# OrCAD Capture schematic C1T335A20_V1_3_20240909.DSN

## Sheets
1 005_SDM: size A4; title: TELINK; rev: V1.3; note: C1T335A20
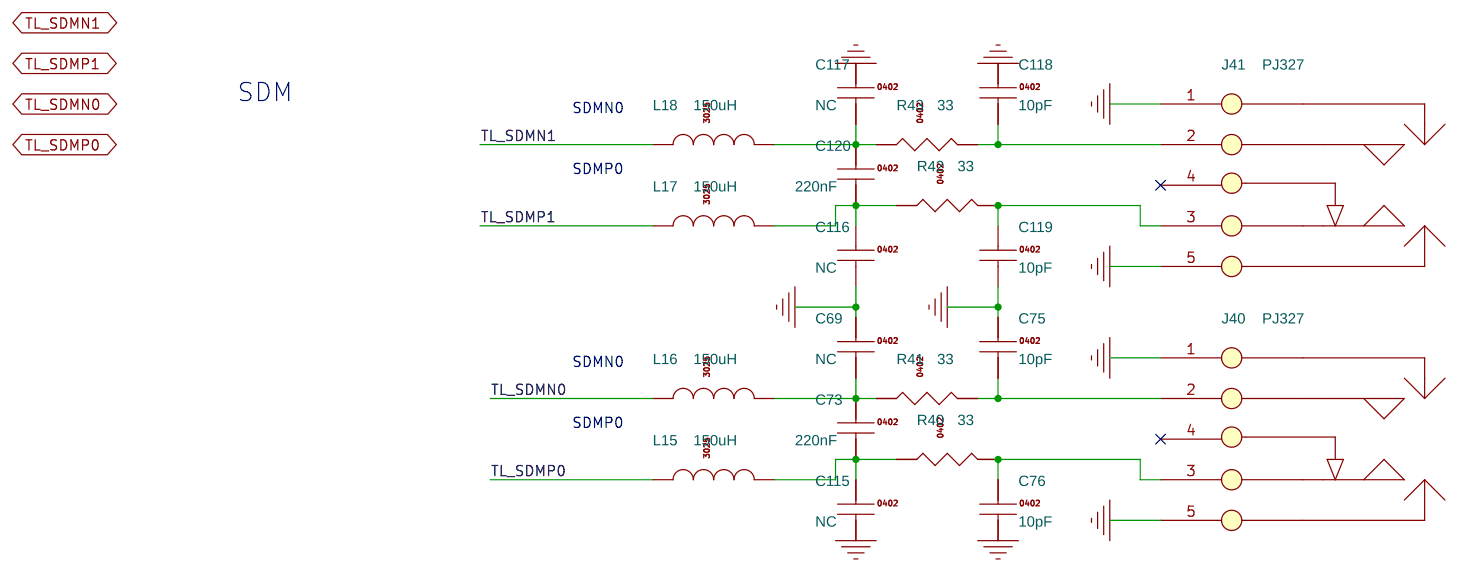
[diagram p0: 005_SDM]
2 000_LOG
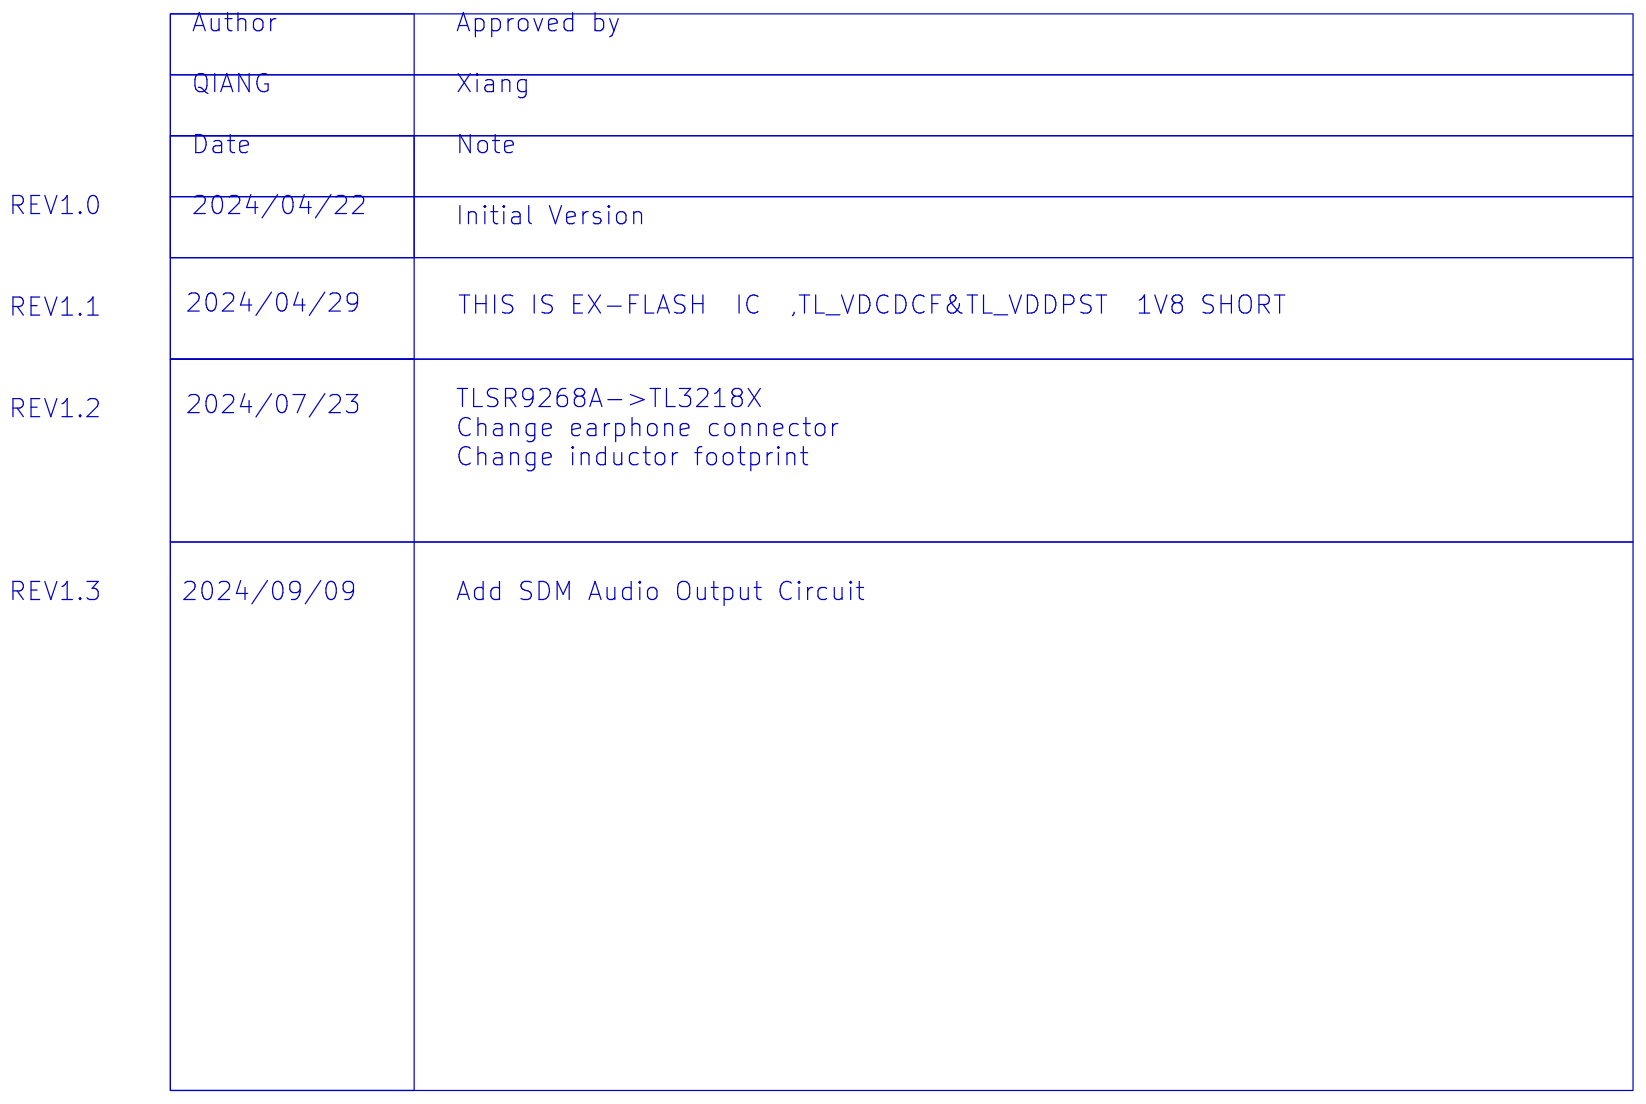
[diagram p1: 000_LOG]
3 001_STR
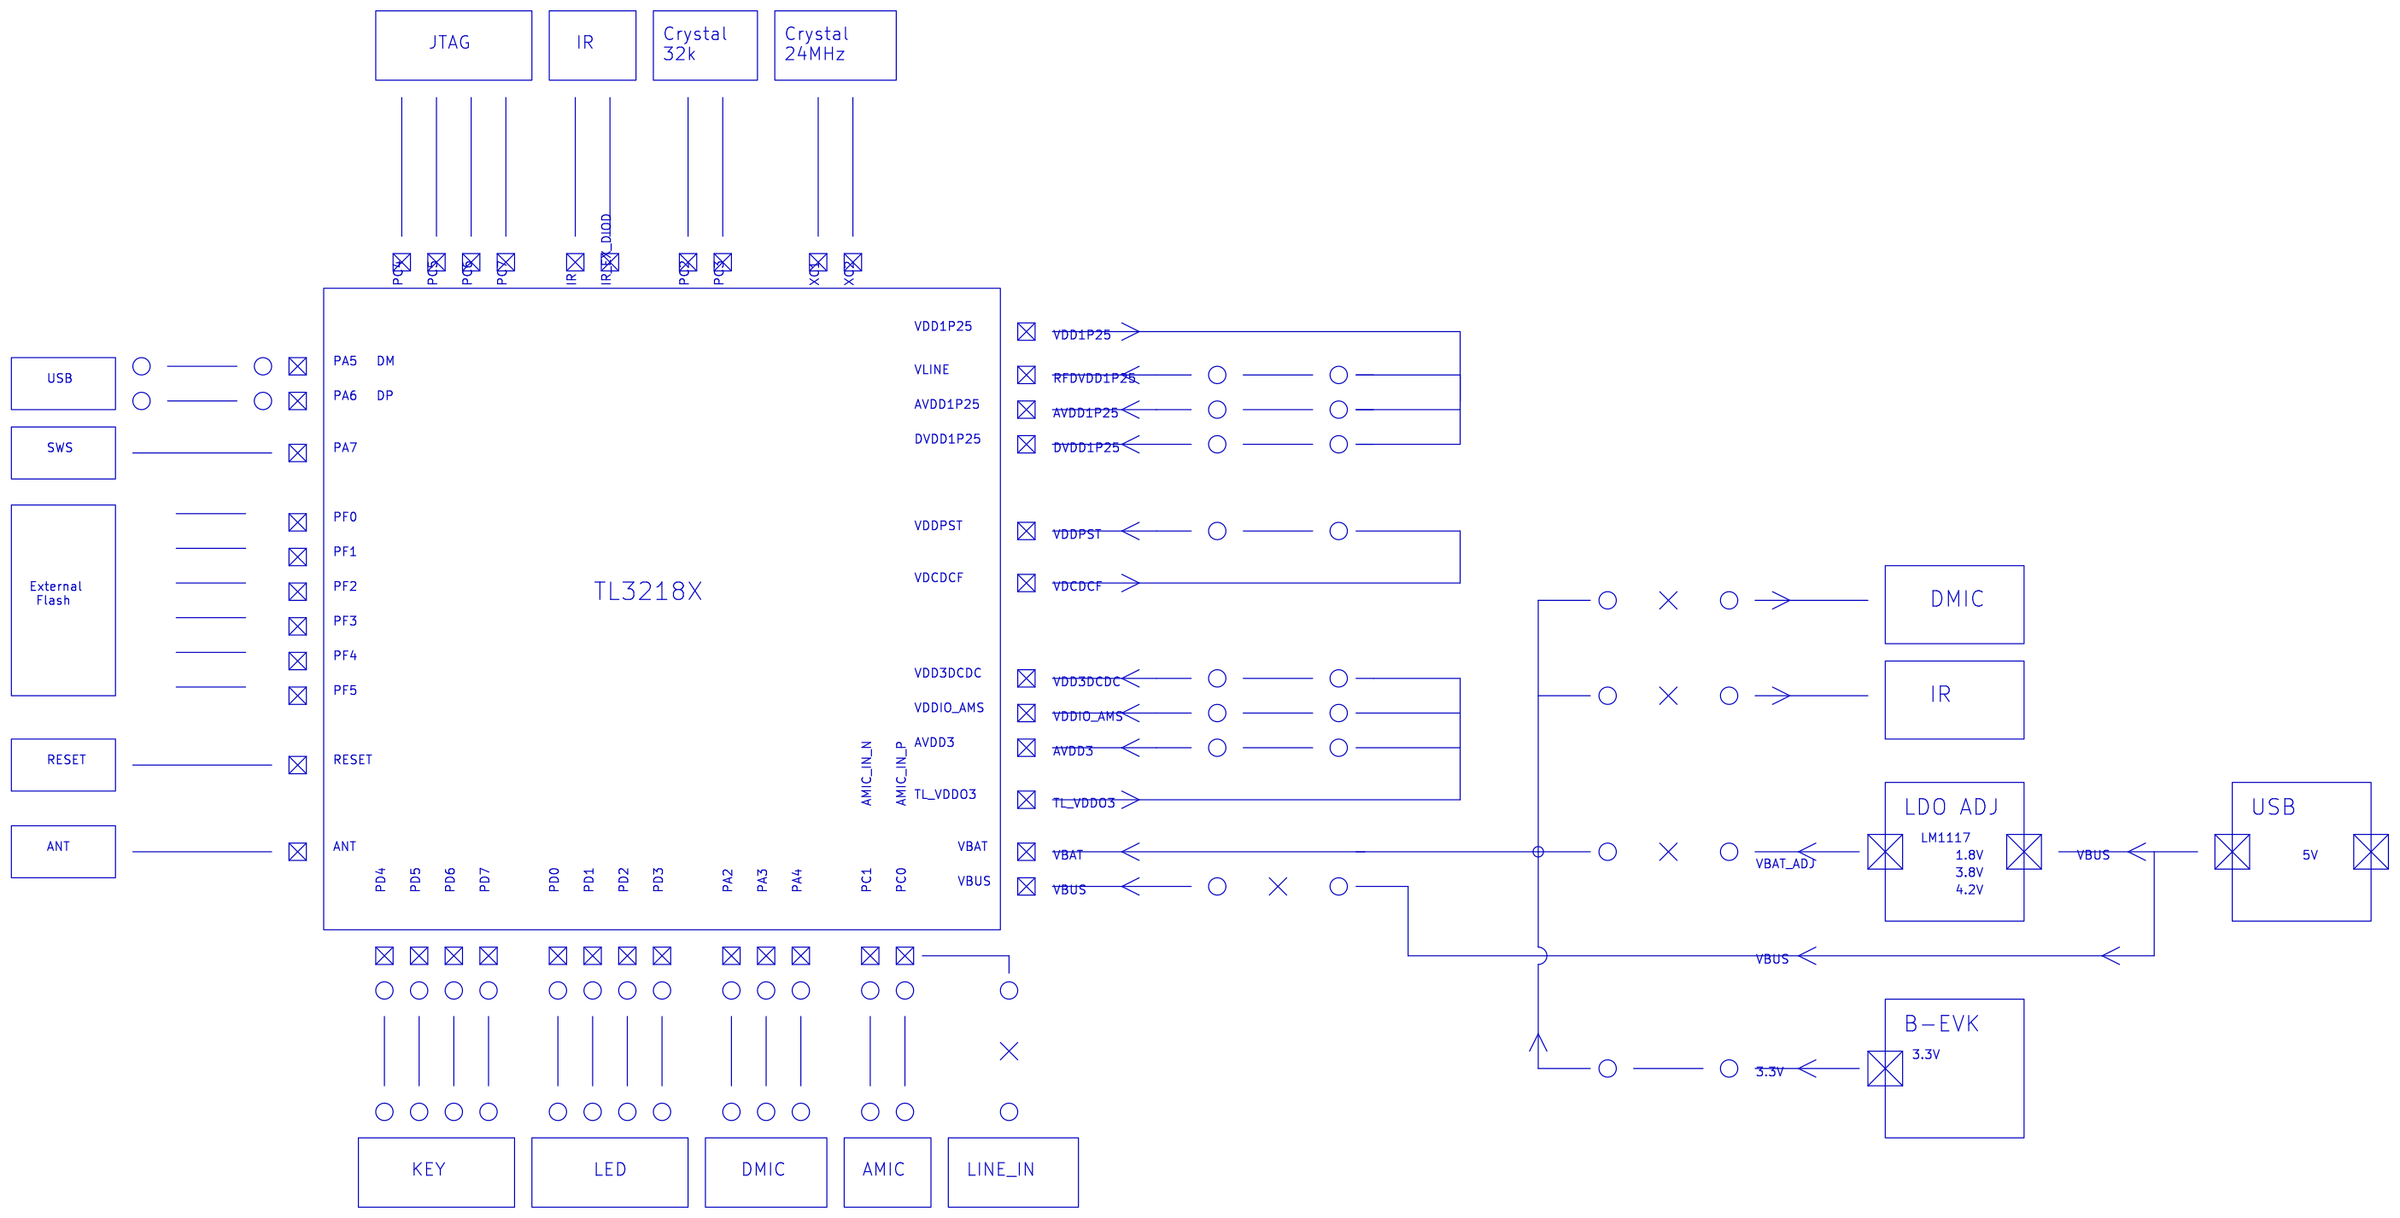
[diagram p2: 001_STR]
4 002_MAIN: size A3
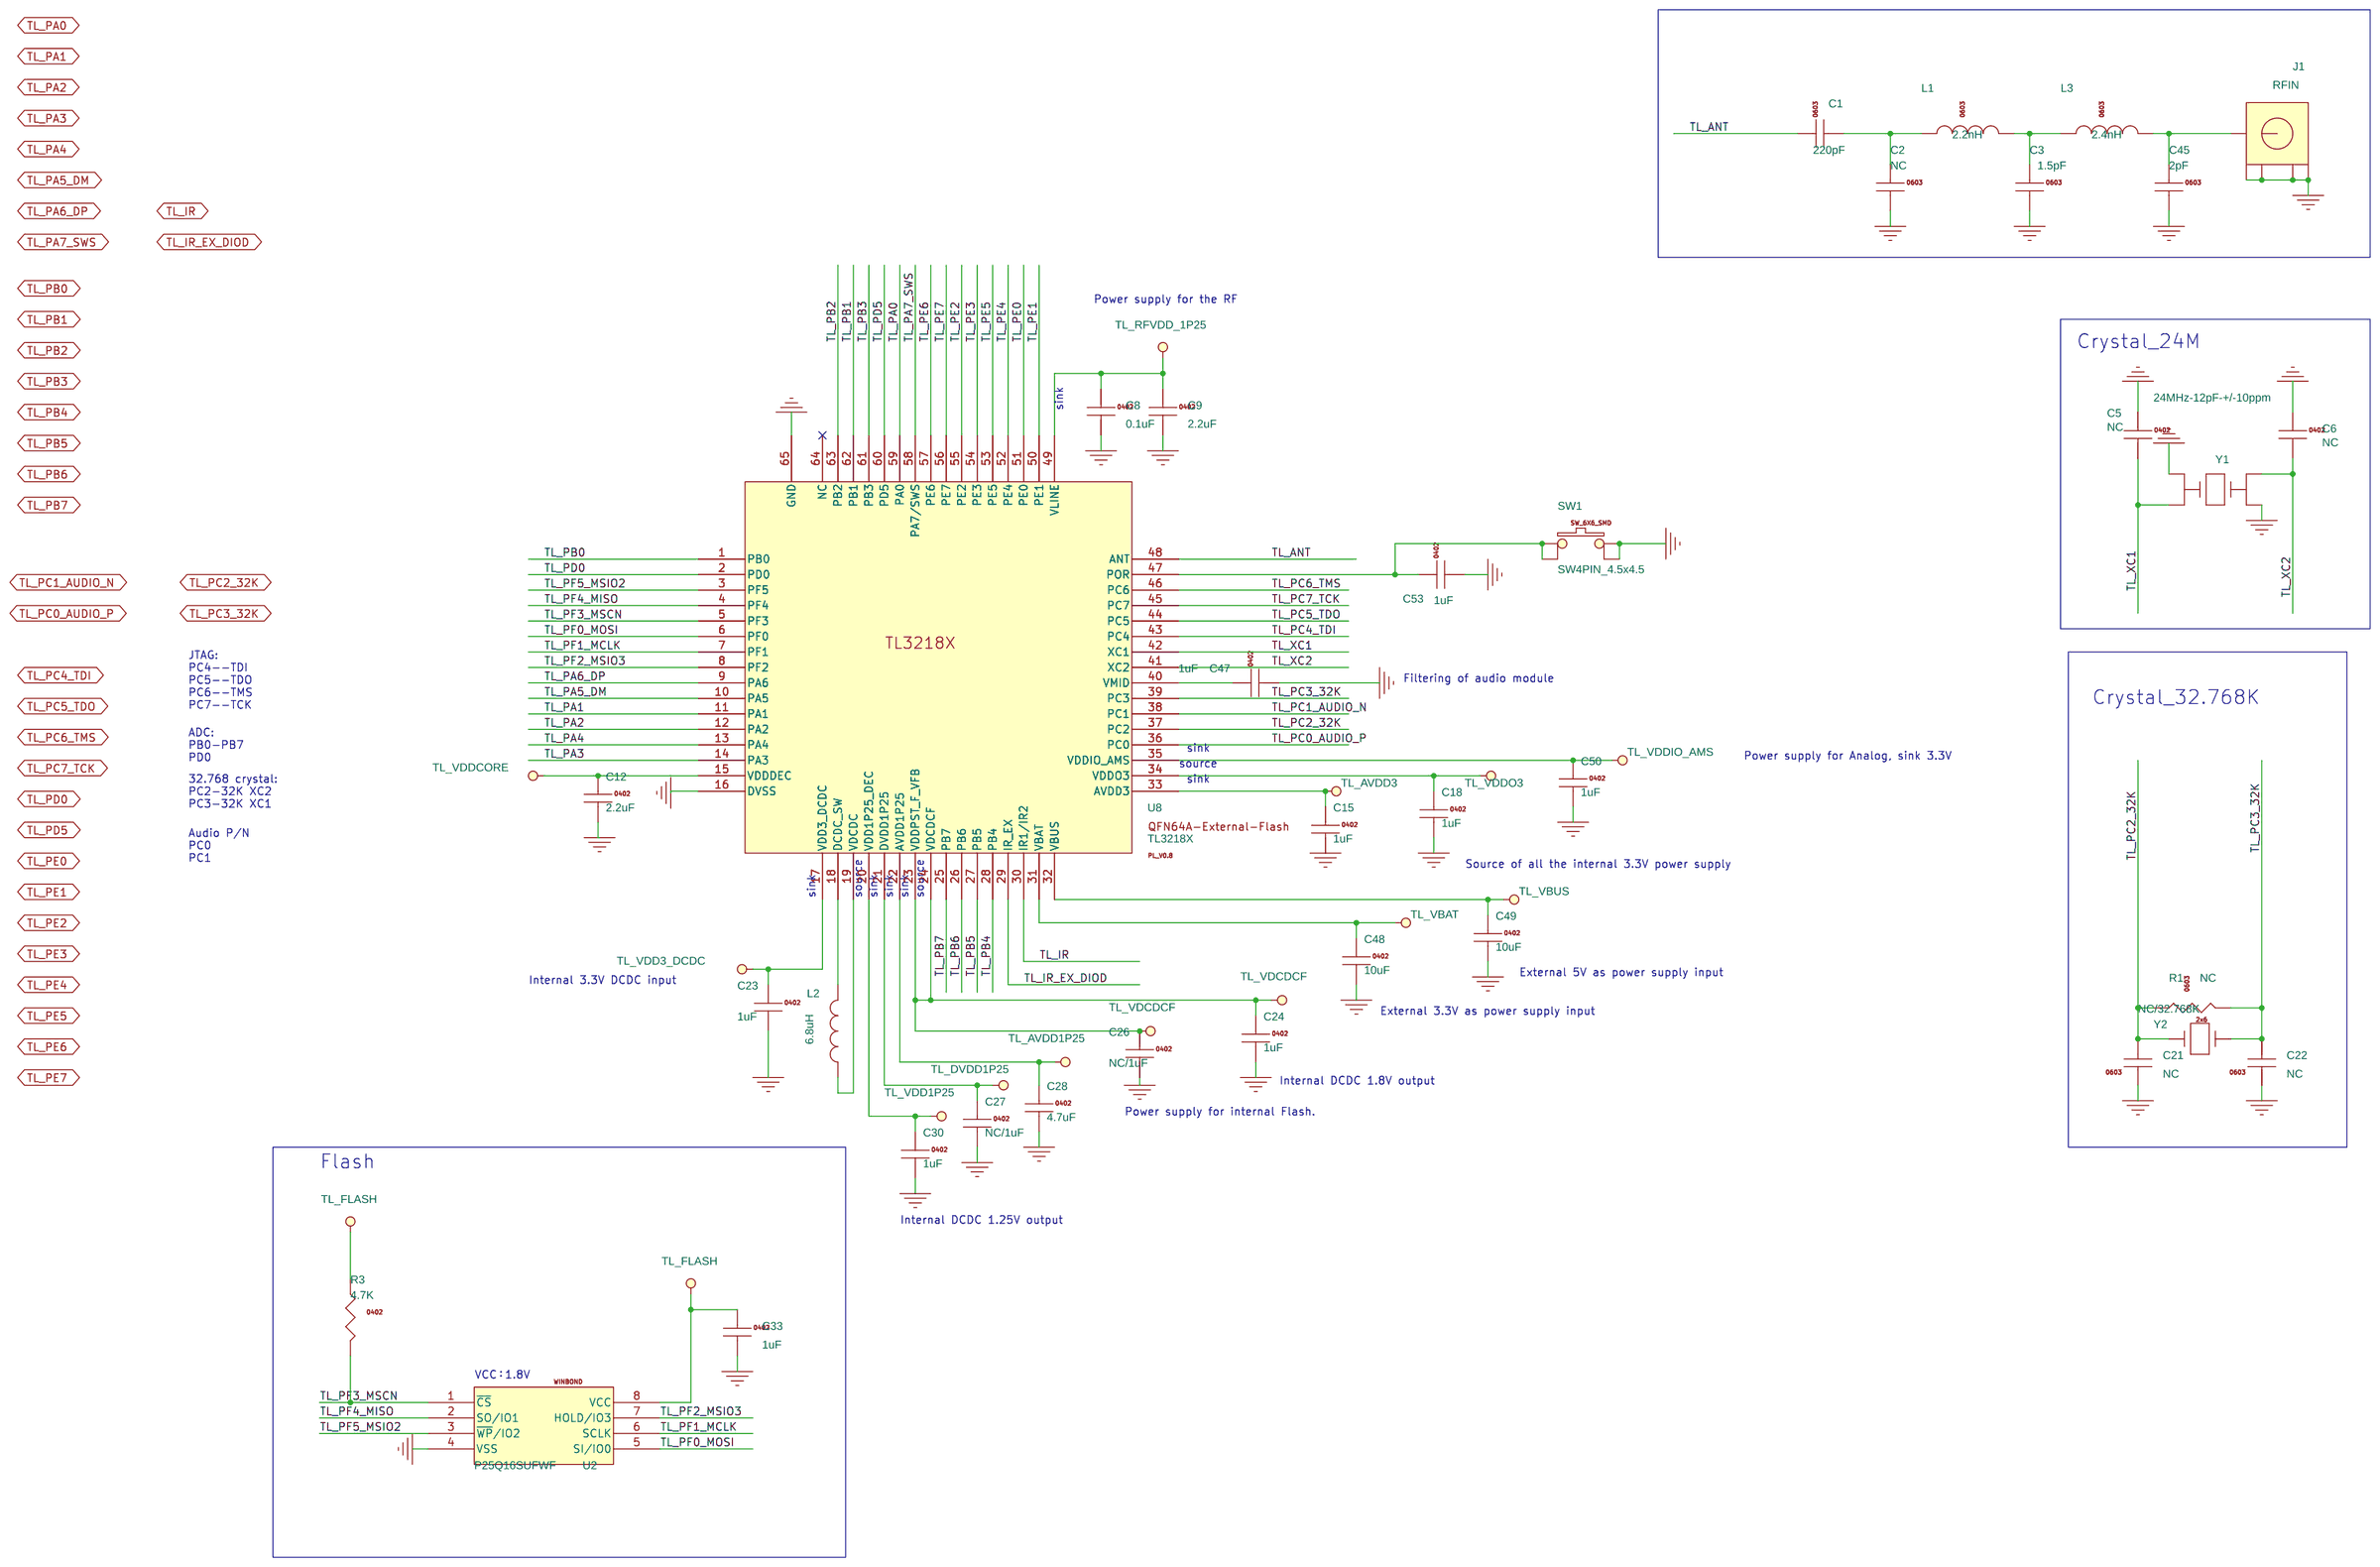
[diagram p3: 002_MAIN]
5 003_INTERFACE: size A3
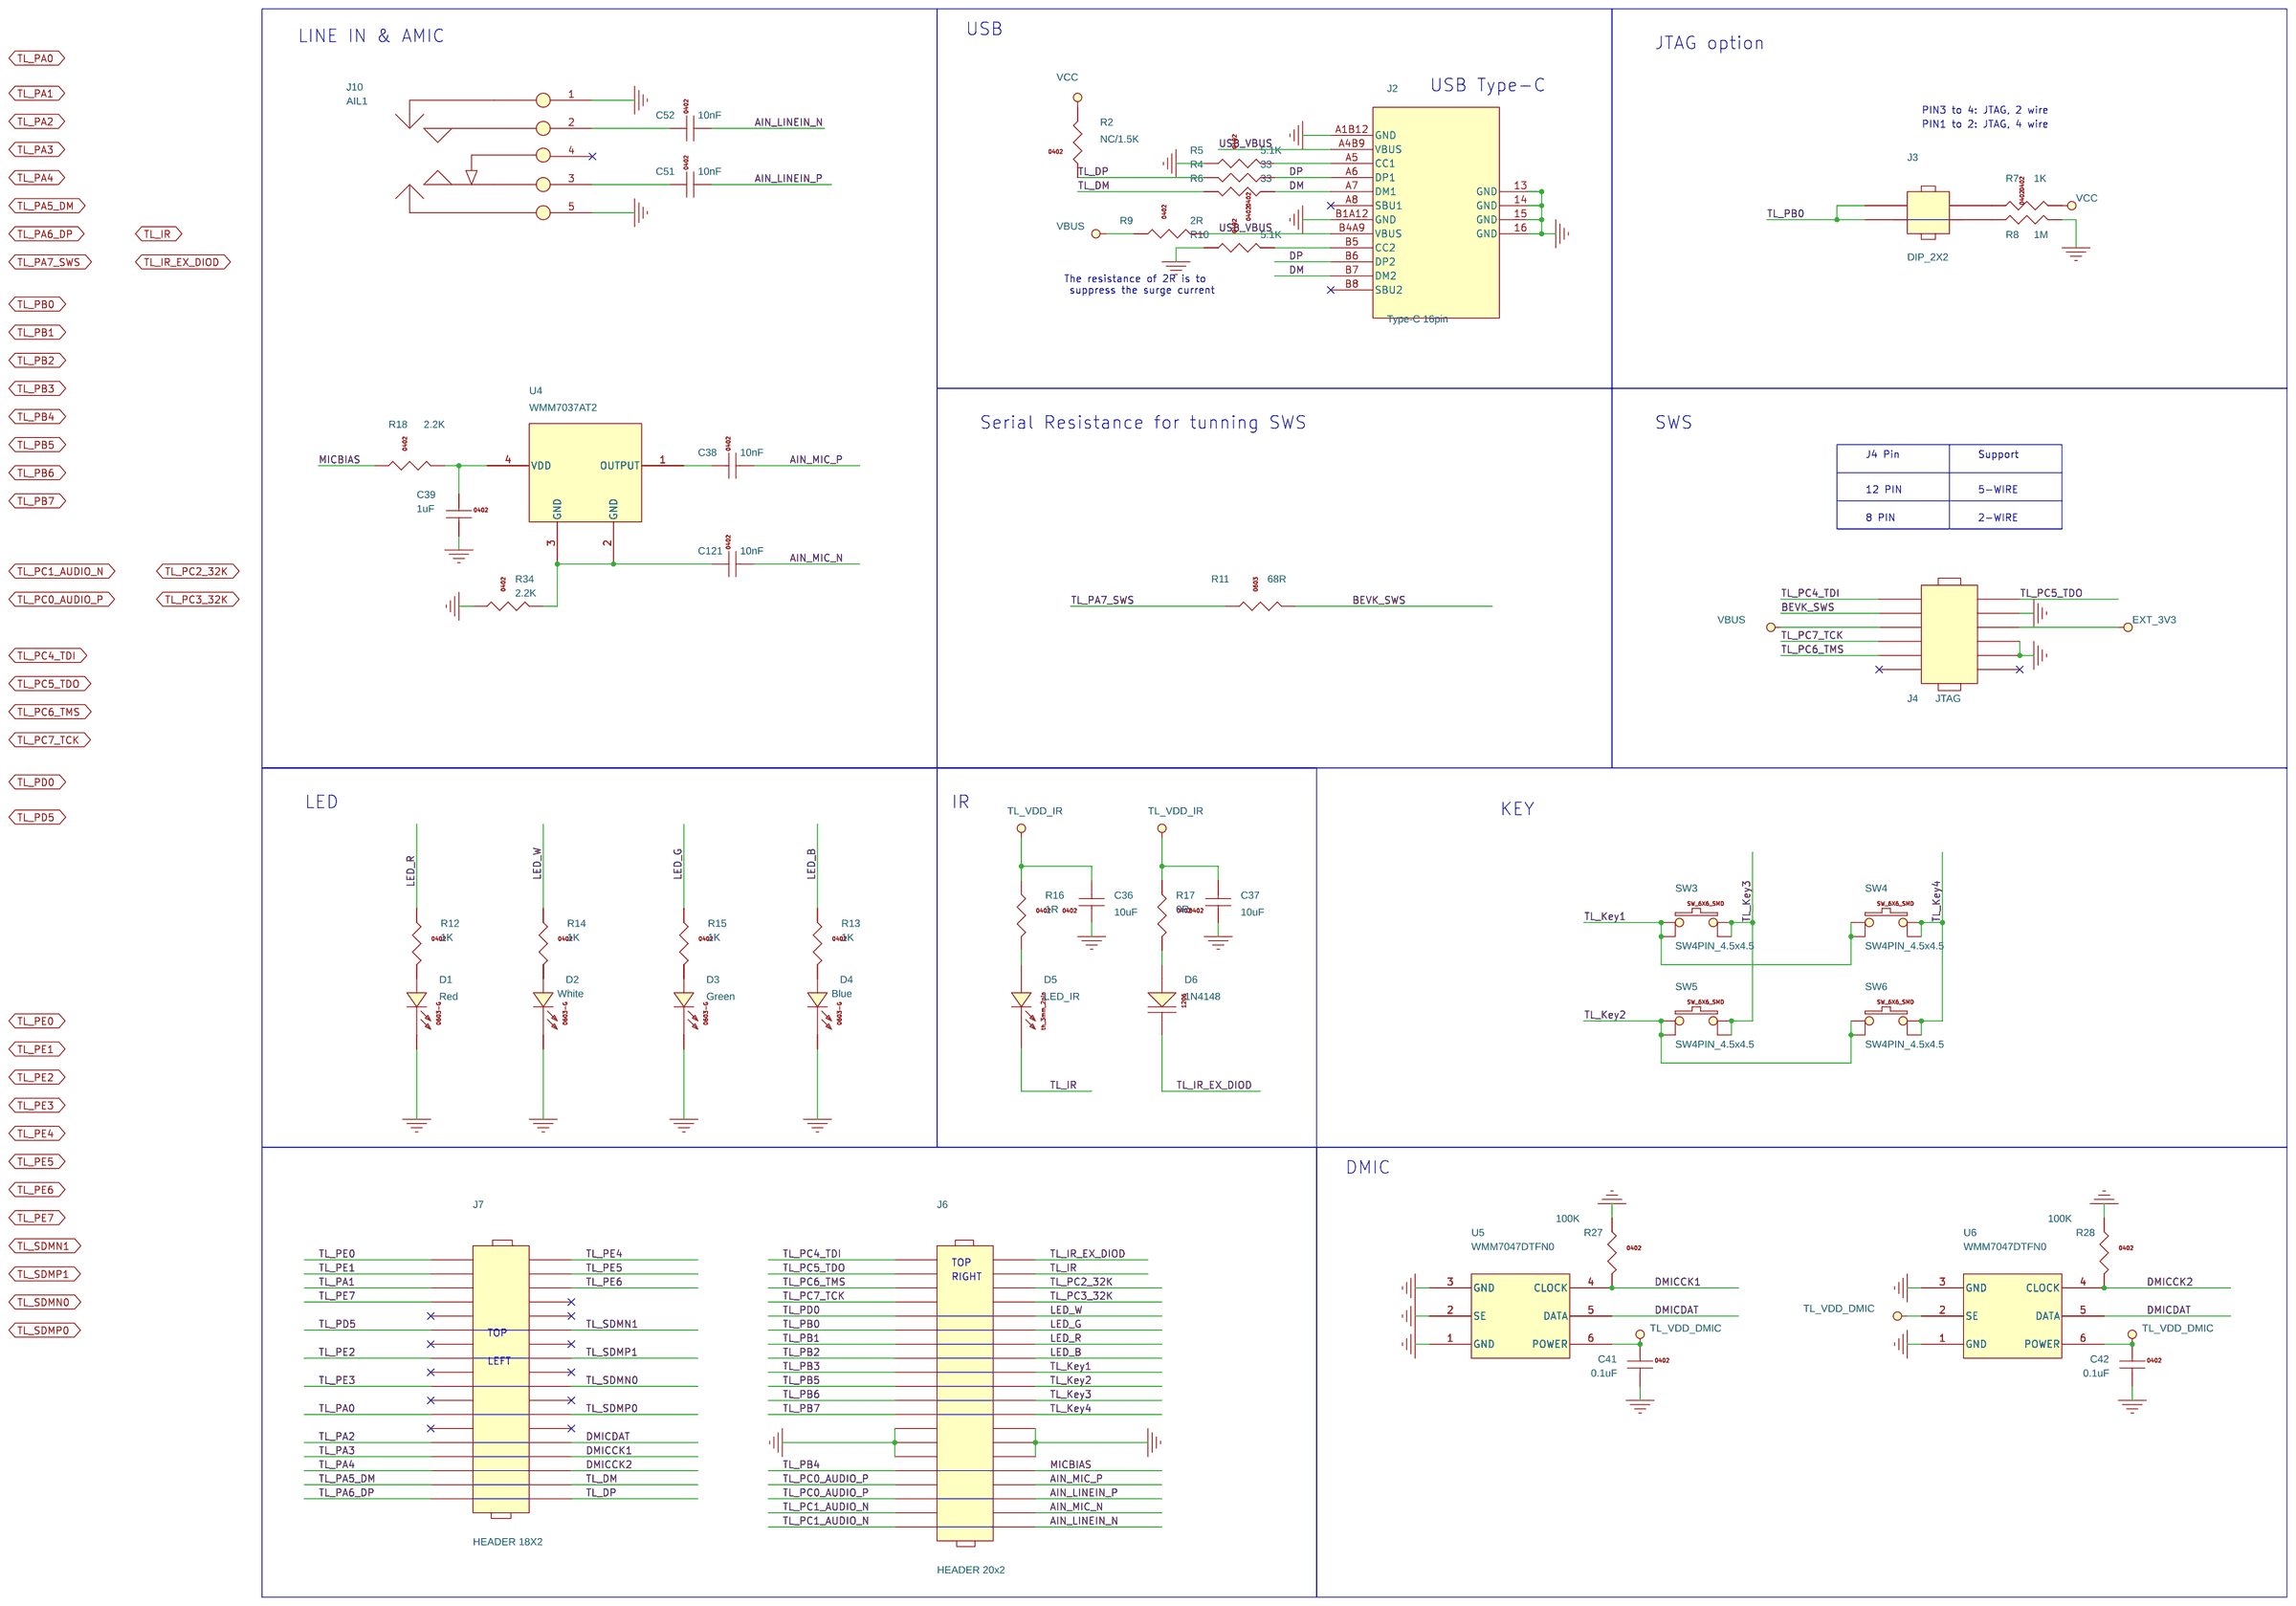
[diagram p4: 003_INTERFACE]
6 004_POWER: size A4
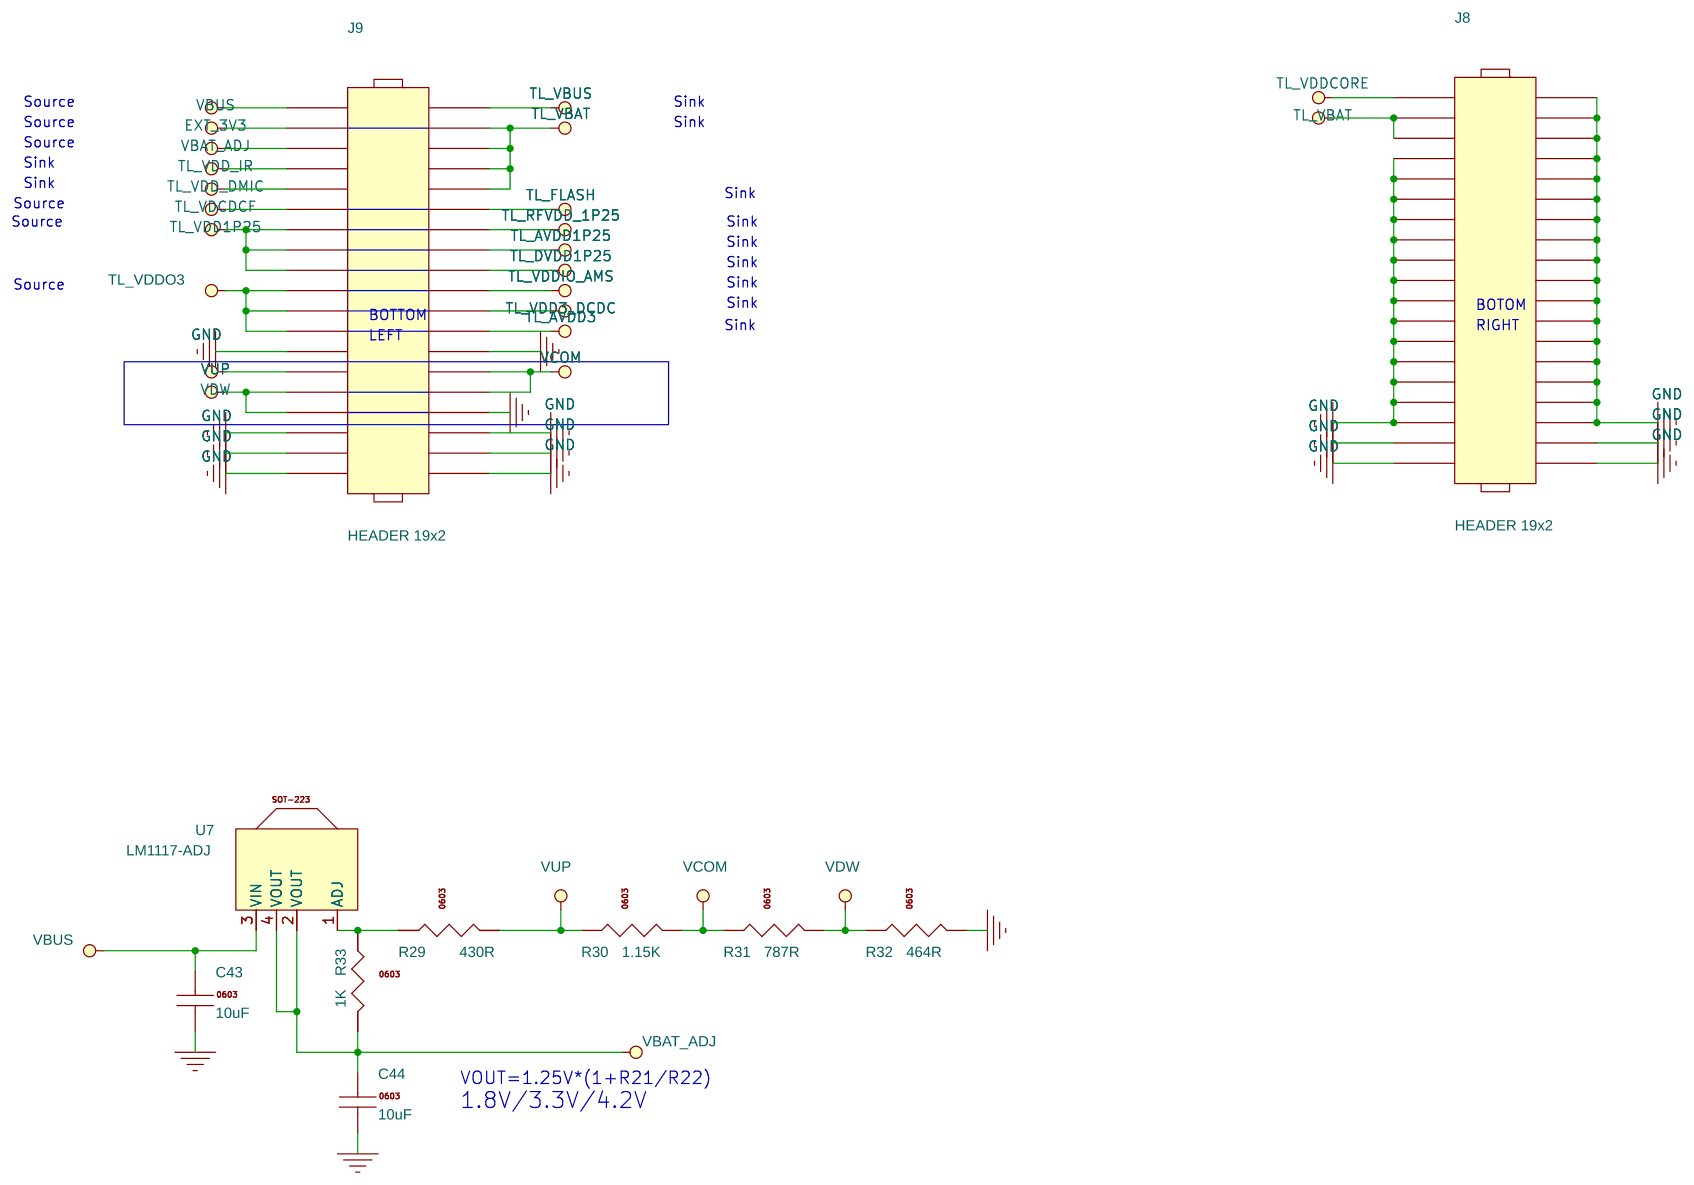
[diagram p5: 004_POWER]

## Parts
sheet 002_MAIN
C1  220pF  [0402]
C2  NC  [0402]
C3  1.5pF  [0402]
C5  NC  [0402]
C6  NC  [0402]
C8  0.1uF  [0402]
C9  2.2uF  [0402]
C12  2.2uF  [0402]
C15  1uF  [0402]
C18  1uF  [0402]
C21  NC  [0402]
C22  NC  [0402]
C23  1uF  [0402]
C24  1uF  [0402]
C26  NC/1uF  [0402]
C27  NC/1uF  [0402]
C28  4.7uF  [0402]
C30  1uF  [0402]
C33  1uF  [0402]
C45  2pF  [0402]
C47  1uF  [0402]
C48  10uF  [0603C]
C49  10uF  [0603C]
C50  1uF  [0402]
C53  1uF  [0402]
J1  RFIN  [SMA-H]
L1  2.2nH  [0402]
L2  6.8uH  [0805l_0717]
L3  2.4nH  [0402]
R1  NC  [0402]
R3  4.7K  [0402]
SW1  SW4PIN_4.5x4.5  [SW_6X6_SMD]
U2  P25Q16SUFWF  [W25X10_20_40BL]
U8  TL3218X  [qfn_8x8_64pin_0p4_4p50x4p50]
Y1  24MHz-12pF-+/-10ppm  [OSCCC250X320X110]
Y2  NC/32.768K  [OSC_2x6]
sheet 003_INTERFACE
C36  10uF  [0603C]
C37  10uF  [0603C]
C38  10nF  [0402]
C39  1uF  [0402]
C41  0.1uF  [0402]
C42  0.1uF  [0402]
C51  10nF  [0402]
C52  10nF  [0402]
C121  10nF  [0402]
D1  Red  [0603-LED]
D2  White  [0603-LED]
D3  Green  [0603-LED]
D4  Blue  [0603-LED]
D5  LED_IR  [led_th_2p54mm_2pin]
D6  1N4148  [SOD80]
J2  Type-C 16pin  [type_c_cq_105pwb]
J3  DIP_2X2  [DipSwitch_2p54_7p62_2x2]
J4  JTAG  [hdr254f-2x6x850]
J6  HEADER 20x2  [smd254m-2x20_rx1_30y2_40]
J7  HEADER 18X2  [smd254m-2x18_rx1_30y2_40]
J10  AIL1  [PJ-327]
R2  NC/1.5K  [0402]
R4  33  [0402]
R5  5.1K  [0402]
R6  33  [0402]
R7  1K  [0402]
R8  1M  [0402]
R9  2R  [0402]
R10  5.1K  [0402]
R11  68R  [0402]
R12  1K  [0402]
R13  1K  [0402]
R14  1K  [0402]
R15  1K  [0402]
R16  1R  [1206R]
R17  0R  [0402]
R18  2.2K  [0402]
R27  100K  [0402]
R28  100K  [0402]
R34  2.2K  [0402]
SW3  SW4PIN_4.5x4.5  [SW_6X6_SMD]
SW4  SW4PIN_4.5x4.5  [SW_6X6_SMD]
SW5  SW4PIN_4.5x4.5  [SW_6X6_SMD]
SW6  SW4PIN_4.5x4.5  [SW_6X6_SMD]
U4  WMM7037AT2  [ga_bfa423_a83]
U5  WMM7047DTFN0  [DMIC_SPM0423HM4H-WB]
U6  WMM7047DTFN0  [DMIC_SPM0423HM4H-WB]
sheet 004_POWER
C43  10uF  [0603c]
C44  10uF  [0603C]
J8  HEADER 19x2  [HDR2X19-2R54-SM-M]
J9  HEADER 19x2  [HDR2X19-2R54-SM-M]
R29  430R  [0402]
R30  1.15K  [0402]
R31  787R  [0402]
R32  464R  [0402]
R33  1K  [0402]
U7  LM1117-ADJ  [sot-223]
sheet 005_SDM
C69  NC  [0402]
C73  220nF  [0402]
C75  10pF  [0402]
C76  10pF  [0402]
C115  NC  [0402]
C116  NC  [0402]
C117  NC  [0402]
C118  10pF  [0402]
C119  10pF  [0402]
C120  220nF  [0402]
J40  PJ327  [PJ-327]
J41  PJ327  [PJ-327]
L15  150uH  [INDM3025X25]
L16  150uH  [INDM3025X25]
L17  150uH  [INDM3025X25]
L18  150uH  [INDM3025X25]
R40  33  [0402R]
R41  33  [0402R]
R42  33  [0402R]
R43  33  [0402R]

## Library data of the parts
C1-C3 C21 C22 C45 = C1608_NC
C5 C6 C69 C115-C117 = C1005_NC
C8 C9 C12 C15 C18 C23 C24 C26-C28 C30 C33 C36-C39 C47-C53 C121 = C1005X5R1C104K
J1 = SMA_JACK_2: PART: RF
L1 L3 = MLK1608_000R
L2 = IND_0
R1 R11 = RS0603K102JT
R3 R7 R8 R18 R27 R28 R34 = RS0402K104JT
SW1 SW3-SW6 = SW_6X6_SMD_0
U2 = GD25LD40C_0
U8 = TL321X_0
Y1 = CRYSTAL4_SM_0
Y2 = OSC_2x6_2pin_16Mhz
C41 C42 = C1005X5R1C104K_1
D1-D4 = 0603D_Green
D5 = Led_Th_3mm_1
D6 = Diode_1N4148
J2 = Type-C_16pin_0
J3 = HEADER_2X2_0
J4 = HEADER_6X2
J6 = HEADER_20x2_M
J7 = HEADER_18X2
J10 J40 J41 = PJ327_2
R2 = RS0402K152JT
R4-R6 R9 R10 = RS0402K330JT: ROOM: USB
R12-R17 = RS0402K102JT
U4 = MULPS4CX-RM5_0
U5 U6 = LD1117_SO_0
C43 = C1608X5R0J106M
C44 = C1608X5R1C105M
J8 J9 = HEADER_19x2
R29-R33 = RS0603K104JT
U7 = XC62FP3302_0.3V_SOT-89
C73 C120 = C1005X5R1C224M
C75 C76 C118 C119 = C1005C0G1H100D
L15-L18 = IND_150uH_3025
R40-R43 = RS0402K330JT

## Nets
GND: C2.2 C3.2 C5.1 C6.1 C8.2 C9.2 C12.2 C15.2 C18.2 C21.1 C22.1 C23.2 C24.2 C26.2 C27.2 C28.2 C30.2 C33.2 C36.1 C37.1 C39.2 C41.2 C42.2 C43.2 C44.2 C45.2 C47.2 C48.2 C49.2 C50.2 C53.2 C69.1 C75.1 C76.2 C115.2 C116.2 C117.1 C118.1 C119.2 D1.C(CATHODE) D2.C(CATHODE) D3.C(CATHODE) D4.C(CATHODE) J1.2 J1.3 J1.4 J1.5 J2.13(GND) J2.14(GND) J2.15(GND) J2.16(GND) J2.A1B12(GND) J2.B1A12(GND) J4.3 J4.5 J4.9 J6.25 J6.26 J6.27 J6.28 J6.29 J6.30 J8.1 J8.3 J8.5 J8.7 J8.8 J8.9 J8.10 J8.11 J8.12 J8.13 J8.14 J8.15 J8.16 J8.17 J8.18 J8.19 J8.20 J8.21 J8.22 J8.23 J8.24 J8.25 J8.26 J8.27 J8.28 J8.29 J8.30 J8.31 J8.32 J8.33 J8.34 J8.35 J8.36 J8.37 J8.38 J9.25 J9.26 J9.31 J9.33 J9.34 J9.35 J9.36 J9.37 J9.38 J10.1 J10.5 J40.1 J40.5 J41.1 J41.5 R5.1 R8.2 R10.1 R27.1 R28.1 R32.2 R34.1 SW1.3 SW1.4 U2.4(VSS) U5.1(GND) U5.2(SE) U5.3(GND) U6.1(GND) U6.3(GND) U8.16(DVSS) U8.65(GND) Y1.2 Y1.4
VBAT_ADJ: C44.1 J9.6 R33.2 U7.2(VOUT) U7.4(VOUT)
VBUS: C43.1 J4.8 J9.2 R9.1 U7.3(VIN)
AIN_LINEIN_N: C52.2 J6.39
AIN_LINEIN_P: C51.2 J6.35
AIN_MIC_N: C121.2 J6.37
AIN_MIC_P: C38.2 J6.33
BEVK_SWS: J4.10 R11.2
DM: J2.A7(DM1) J2.B7(DM2) R6.1
DMICCK1: J7.29 R27.2 U5.4(CLOCK)
DMICCK2: J7.31 R28.2 U6.4(CLOCK)
DMICDAT: J7.27 U5.5(DATA) U6.5(DATA)
DP: J2.A6(DP1) J2.B6(DP2) R4.1
EXT_3V3: J4.7 J9.4
LED_B: J6.15 R13.1
LED_G: J6.11 R15.1
LED_R: J6.13 R12.1
LED_W: J6.9 R14.1
MICBIAS: J6.31 R18.1
TL_ANT: C1.1 U8.48(ANT)
TL_AVDD1P25: C28.1 J9.15 U8.22(AVDD1P25)
TL_AVDD3: C15.1 J9.23 U8.33(AVDD3)
TL_DM: J7.33 R6.2
TL_DP: J7.35 R2.1 R4.2
TL_DVDD1P25: C27.1 J9.17 U8.21(DVDD1P25)
TL_FLASH: C33.1 J9.11 R3.1 U2.8(VCC)
TL_IR: U8.30(IR1/IR2)
TL_IR (page 003_INTERFACE): D5.C(CATHODE) J6.3
TL_IR_EX_DIOD: U8.29(IR_EX)
TL_IR_EX_DIOD (page 003_INTERFACE): D6.C J6.1
TL_Key1: J6.17 SW3.1 SW3.2 SW4.1 SW4.2
TL_Key2: J6.19 SW5.1 SW5.2 SW6.1 SW6.2
TL_Key3: J6.21 SW3.3 SW3.4 SW5.3 SW5.4
TL_Key4: J6.23 SW4.3 SW4.4 SW6.3 SW6.4
TL_PA0: U8.59(PA0)
TL_PA0 (page 003_INTERFACE): J7.24
TL_PA1: U8.11(PA1)
TL_PA1 (page 003_INTERFACE): J7.6
TL_PA2: U8.12(PA2)
TL_PA2 (page 003_INTERFACE): J7.28
TL_PA3: U8.14(PA3)
TL_PA3 (page 003_INTERFACE): J7.30
TL_PA4: U8.13(PA4)
TL_PA4 (page 003_INTERFACE): J7.32
TL_PA5_DM: U8.10(PA5)
TL_PA5_DM (page 003_INTERFACE): J7.34
TL_PA6_DP: U8.9(PA6)
TL_PA6_DP (page 003_INTERFACE): J7.36
TL_PA7_SWS: U8.58(PA7/SWS)
TL_PA7_SWS (page 003_INTERFACE): R11.1
TL_PB0: U8.1(PB0)
TL_PB0 (page 003_INTERFACE): J3.1 J3.3 J6.12
TL_PB1: U8.62(PB1)
TL_PB1 (page 003_INTERFACE): J6.14
TL_PB2: U8.63(PB2)
TL_PB2 (page 003_INTERFACE): J6.16
TL_PB3: U8.61(PB3)
TL_PB3 (page 003_INTERFACE): J6.18
TL_PB4: U8.28(PB4)
TL_PB4 (page 003_INTERFACE): J6.32
TL_PB5: U8.27(PB5)
TL_PB5 (page 003_INTERFACE): J6.20
TL_PB6: U8.26(PB6)
TL_PB6 (page 003_INTERFACE): J6.22
TL_PB7: U8.25(PB7)
TL_PB7 (page 003_INTERFACE): J6.24
TL_PC0_AUDIO_P: U8.36(PC0)
TL_PC0_AUDIO_P (page 003_INTERFACE): J6.34 J6.36
TL_PC1_AUDIO_N: U8.38(PC1)
TL_PC1_AUDIO_N (page 003_INTERFACE): J6.38 J6.40
TL_PC2_32K: C21.2 R1.1 U8.37(PC2) Y2.1
TL_PC2_32K (page 003_INTERFACE): J6.5
TL_PC3_32K: C22.2 R1.2 U8.39(PC3) Y2.2
TL_PC3_32K (page 003_INTERFACE): J6.7
TL_PC4_TDI: U8.43(PC4)
TL_PC4_TDI (page 003_INTERFACE): J4.12 J6.2
TL_PC5_TDO: U8.44(PC5)
TL_PC5_TDO (page 003_INTERFACE): J4.11 J6.4
TL_PC6_TMS: U8.46(PC6)
TL_PC6_TMS (page 003_INTERFACE): J4.4 J6.6
TL_PC7_TCK: U8.45(PC7)
TL_PC7_TCK (page 003_INTERFACE): J4.6 J6.8
TL_PD0: U8.2(PD0)
TL_PD0 (page 003_INTERFACE): J6.10
TL_PD5: U8.60(PD5)
TL_PD5 (page 003_INTERFACE): J7.12
TL_PE0: U8.51(PE0)
TL_PE0 (page 003_INTERFACE): J7.2
TL_PE1: U8.50(PE1)
TL_PE1 (page 003_INTERFACE): J7.4
TL_PE2: U8.55(PE2)
TL_PE2 (page 003_INTERFACE): J7.16
TL_PE3: U8.54(PE3)
TL_PE3 (page 003_INTERFACE): J7.20
TL_PE4: U8.52(PE4)
TL_PE4 (page 003_INTERFACE): J7.1
TL_PE5: U8.53(PE5)
TL_PE5 (page 003_INTERFACE): J7.3
TL_PE6: U8.57(PE6)
TL_PE6 (page 003_INTERFACE): J7.5
TL_PE7: U8.56(PE7)
TL_PE7 (page 003_INTERFACE): J7.8
TL_PF0_MOSI: U2.5(SI/IO0) U8.6(PF0)
TL_PF1_MCLK: U2.6(SCLK) U8.7(PF1)
TL_PF2_MSIO3: U2.7(HOLD/IO3) U8.8(PF2)
TL_PF3_MSCN: R3.2 U2.1(~{CS}) U8.5(PF3)
TL_PF4_MISO: U2.2(SO/IO1) U8.4(PF4)
TL_PF5_MSIO2: U2.3(~{WP}/IO2) U8.3(PF5)
TL_RFVDD_1P25: C8.1 C9.1 J9.13 U8.49(VLINE)
TL_SDMN0: J7.19
TL_SDMN0 (page 005_SDM): L16.1
TL_SDMN1: J7.11
TL_SDMN1 (page 005_SDM): L18.1
TL_SDMP0: J7.23
TL_SDMP0 (page 005_SDM): L15.1
TL_SDMP1: J7.15
TL_SDMP1 (page 005_SDM): L17.1
TL_VBAT: C48.1 J8.4 J8.6 J9.3 J9.5 J9.7 J9.9 R2.2 U8.31(VBAT)
TL_VBUS: C49.1 J9.1 U8.32(VBUS)
TL_VDCDCF: C24.1 C26.1 J9.12 U8.23(VDDPST_F_VFB) U8.24(VDCDCF)
TL_VDD1P25: C30.1 J9.14 J9.16 J9.18 U8.20(VDD1P25_DEC)
TL_VDD3_DCDC: C23.1 J9.21 U8.17(VDD3_DCDC)
TL_VDD_DMIC: C41.1 C42.1 J9.10 U5.6(POWER) U6.2(SE) U6.6(POWER)
TL_VDD_IR: C36.2 C37.2 J9.8 R16.1 R17.1
TL_VDDCORE: C12.1 J8.2 U8.15(VDDDEC)
TL_VDDIO_AMS: C50.1 J9.19 U8.35(VDDIO_AMS)
TL_VDDO3: C18.1 J9.20 J9.22 J9.24 R7.2 U8.34(VDDO3)
TL_XC1: C5.2 U8.42(XC1) Y1.3
TL_XC2: C6.2 U8.41(XC2) Y1.1
USB_VBUS: J2.A4B9(VBUS) J2.B4A9(VBUS) R9.2
VCOM: J9.27 J9.29 R30.2 R31.1
VDW: J9.30 J9.32 R31.2 R32.1
VUP: J9.28 R29.2 R30.1
N20028206: R29.1 R33.1 U7.1(ADJ)
N20230742: D1.A(ANODE) R12.2
N20265888: C45.1 J1.1 L3.2
N20271178: D5.A(ANODE) R16.2
N20271193: D6.A R17.2
N20290987: L2.1 U8.19(VDCDC)
N20305837: J2.A5(CC1) R5.2
N20305839: J2.B5(CC2) R10.2
N20310970: C1.2 C2.1 L1.1
N20310976: C3.1 L1.2 L3.1
N20338940: C53.1 SW1.1 SW1.2 U8.47(POR)
N20339485: C47.1 U8.40(VMID)
N20340397: L2.2 U8.18(DCDC_SW)
N20354870: C51.1 J10.3
N20355410: C39.1 R18.2 U4.4(VDD)
N20355416: C121.1 R34.2 U4.2(GND) U4.3(GND)
N20355524: C38.1 U4.1(OUTPUT)
N20367047: C52.1 J10.2
N20378023: J3.2 R8.1
N20378025: J3.4 R7.1
N20394676: C116.1 C120.2 L17.2 R42.1
N20394683: C117.2 C120.1 L18.2 R43.1
N20394695: C119.1 J41.3 R42.2
N20394699: C118.2 J41.2 R43.2
N20394813: C73.2 C115.1 L15.2 R40.1
N20394820: C69.2 C73.1 L16.2 R41.1
N20394832: C76.1 J40.3 R40.2
N20394836: C75.2 J40.2 R41.2
N20397613: D2.A(ANODE) R14.2
N20397615: D3.A(ANODE) R15.2
N20397764: D4.A(ANODE) R13.2

Not connected (* = marked no-connect by the designer): J2 A8(SBU1)* B8(SBU2)*; J4 1* 2*; J7 7* 9* 10* 13* 14* 17* 18* 21* 22* 25* 26*; J10 4*; J40 4*; J41 4*; U8 64(NC)*

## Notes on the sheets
sheet 1
- SDM
- SDMN0
- SDMP0
- SDMN0
- SDMP0
sheet 2
- Author
- Approved by
- QIANG
- Xiang
- Date
- Note
- REV1.0
- 2024/04/22
- Initial Version
- REV1.1
- 2024/04/29
- THIS IS EX-FLASH  IC  ,TL_VDCDCF&TL_VDDPST  1V8 SHORT
- REV1.2
- 2024/07/23
- TLSR9268A->TL3218X
  Change earphone connector
  Change inductor footprint
- REV1.3
- 2024/09/09
- Add SDM Audio Output Circuit
sheet 3
- JTAG
- IR
- Crystal
  32k
- Crystal
  24MHz
- PC4
- PC5
- PC6
- PC7
- IR
- IR_EX_DIOD
- PC2
- PC3
- XC1
- XC2
- VDD1P25
- VDD1P25
- PA5
- DM
- USB
- VLINE
- RFDVDD1P25
- PA6
- DP
- AVDD1P25
- AVDD1P25
- SWS
- PA7
- DVDD1P25
- DVDD1P25
- PF0
- VDDPST
- PF1
- VDDPST
- External
   Flash
- PF2
- TL3218X
- VDCDCF
- VDCDCF
- DMIC
- PF3
- PF4
- VDD3DCDC
- PF5
- VDD3DCDC
- IR
- VDDIO_AMS
- VDDIO_AMS
- AVDD3
- AVDD3
- RESET
- RESET
- TL_VDDO3
- AMIC_IN_N
- AMIC_IN_P
- TL_VDDO3
- LDO ADJ
- USB
- LM1117
- ANT
- ANT
- VBAT
- VBAT
- 1.8V
- VBUS
- 5V
- VBAT_ADJ
- 3.8V
- PD4
- PD5
- PD6
- PD7
- PD0
- PD1
- PD2
- PD3
- PA2
- PA3
- PA4
- PC1
- PC0
- VBUS
- VBUS
- 4.2V
- VBUS
- B-EVK
- 3.3V
- 3.3V
- KEY
- LED
- DMIC
- AMIC
- LINE_IN
sheet 4
- Power supply for the RF
- Crystal_24M
- sink
- JTAG:
  PC4--TDI
  PC5--TDO
  PC6--TMS
  PC7--TCK
- Filtering of audio module
- Crystal_32.768K
- ADC:
  PB0-PB7
  PD0
- sink
- source
- Power supply for Analog, sink 3.3V
- 32.768 crystal:
  PC2-32K XC2
  PC3-32K XC1
- sink
- Audio P/N
  PC0
  PC1
- Source of all the internal 3.3V power supply
- sink
- source
- sink
- sink
- sink
- source
- Internal 3.3V DCDC input
- External 5V as power supply input
- External 3.3V as power supply input
- Internal DCDC 1.8V output
- Power supply for internal Flash.
- Flash
- Internal DCDC 1.25V output
- VCC：1.8V
sheet 5
- LINE IN & AMIC
- USB
- JTAG option
- USB Type-C
- PIN3 to 4: JTAG, 2 wire
- PIN1 to 2: JTAG, 4 wire
- The resistance of 2R is to
   suppress the surge current
- Serial Resistance for tunning SWS
- SWS
- J4 Pin
- Support
- 12 PIN
- 5-WIRE
- 8 PIN
- 2-WIRE
- LED
- IR
- KEY
- DMIC
- TOP
- RIGHT
- TOP
- LEFT
sheet 6
- Source
- Sink
- Source
- Sink
- Source
- Sink
- Source
- Sink
- Sink
- Source
- Sink
- Sink
- Sink
- Source
- Sink
- BOTTOM
- Sink
- Sink
- BOTOM
- RIGHT
- LEFT
- VOUT=1.25V*(1+R21/R22)
- 1.8V/3.3V/4.2V
